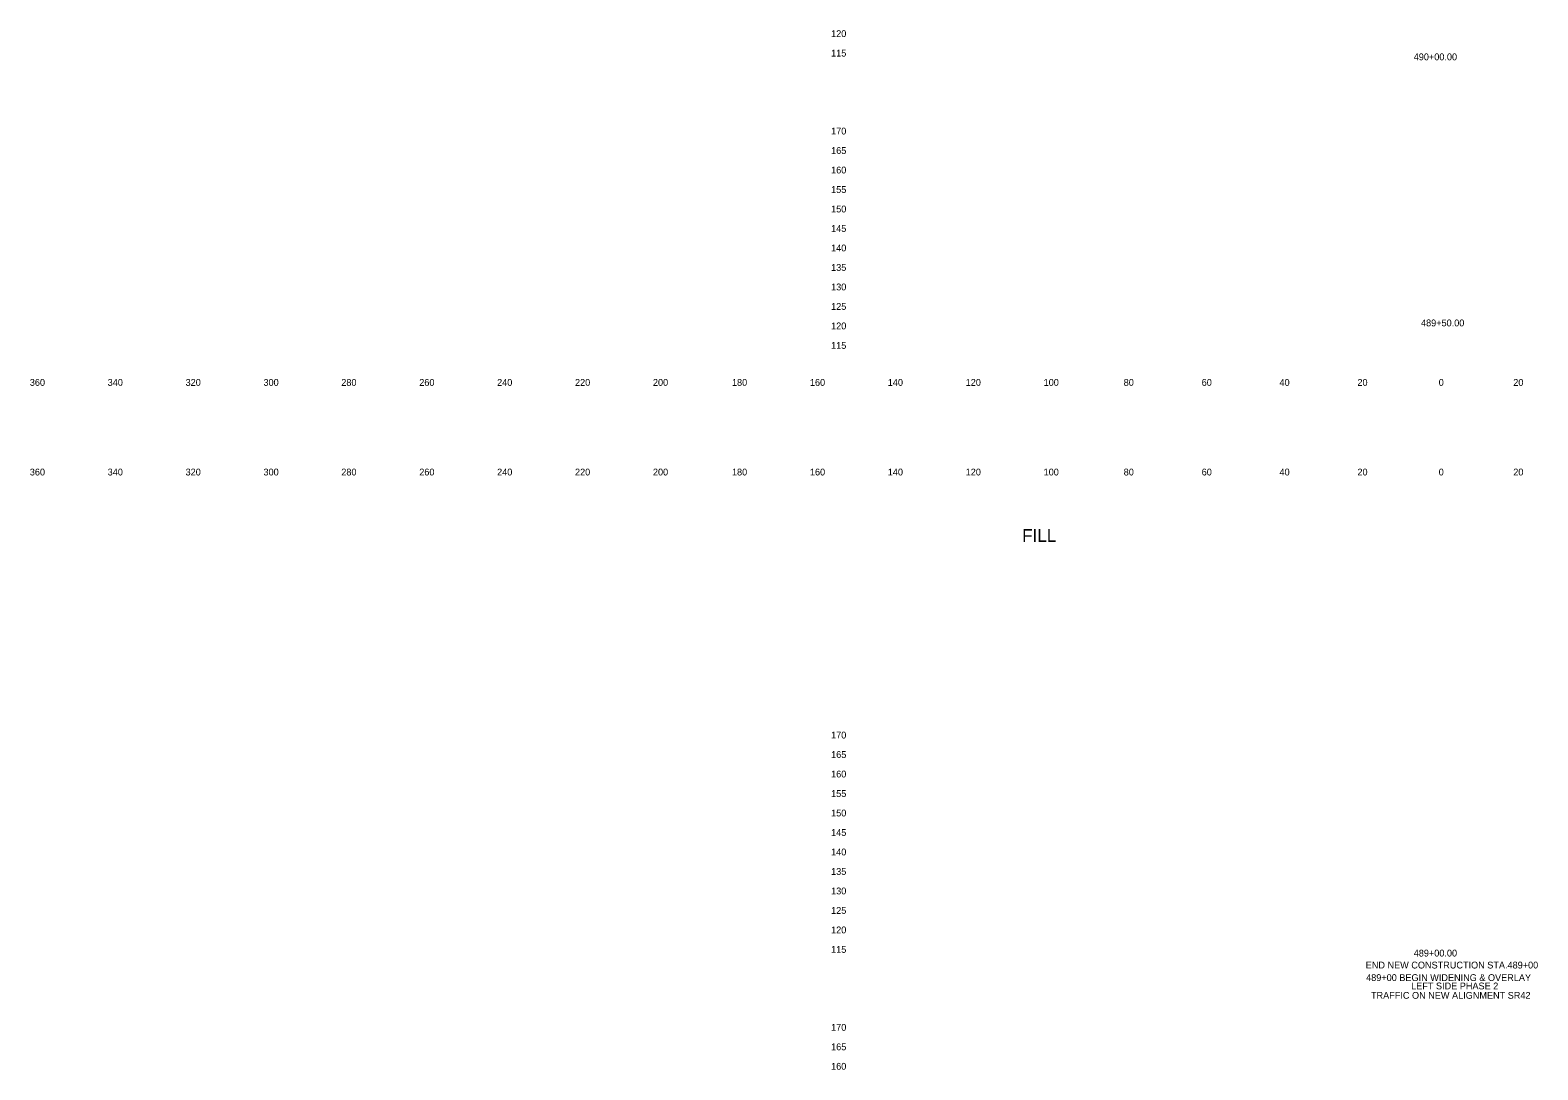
# Model space of a CAD drawing. Extents: x 21281 to 22024, y 6472 to 15208.
# Drawn here: x 21280.5 to 21667.6, y 14119.8 to 14386.6 of the extents above; entities that cross this region are included whole.
import ezdxf

# ---------------------------------------------------------------- set-up
doc = ezdxf.new("R2010")
doc.units = 0
for name, color, linetype in [('XS_SHEET_LABELS_ELEVATION', 7, 'Continuous'), ('XS_SHEET_LABELS_OFFSET', 7, 'Continuous'), ('XS_SHEET_LABELS_STATION', 7, 'Continuous')]:
    doc.layers.add(name, color=color, linetype=linetype)

msp = doc.modelspace()

# ---------------------------------------------------------------- texts
at = {"layer": 'XS_SHEET_LABELS_ELEVATION'}
for s, p in [('  120  ', (21484.84, 14384.84)), ('  115  ', (21484.84, 14379.84)), ('  170  ', (21484.84, 14359.84)), ('  165  ', (21484.84, 14354.84)), ('  160  ', (21484.84, 14349.84)), ('  155  ', (21484.84, 14344.84)), ('  150  ', (21484.84, 14339.84)), ('  145  ', (21484.84, 14334.84)), ('  140  ', (21484.84, 14329.84)), ('  135  ', (21484.84, 14324.84)), ('  130  ', (21484.84, 14319.84)), ('  125  ', (21484.84, 14314.84)), ('  120  ', (21484.84, 14309.84)), ('  115  ', (21484.84, 14304.84)), ('  170  ', (21484.84, 14204.84)), ('  165  ', (21484.84, 14199.84)), ('  160  ', (21484.84, 14194.84)), ('  155  ', (21484.84, 14189.84)), ('  150  ', (21484.84, 14184.84)), ('  145  ', (21484.84, 14179.84)), ('  140  ', (21484.84, 14174.84)), ('  135  ', (21484.84, 14169.84)), ('  130  ', (21484.84, 14164.84)), ('  125  ', (21484.84, 14159.84)), ('  120  ', (21484.84, 14154.84)), ('  115  ', (21484.84, 14149.84)), ('  170  ', (21484.84, 14129.84)), ('  165  ', (21484.84, 14124.84)), ('  160  ', (21484.84, 14119.84))]:
    msp.add_text(s, height=1.75, dxfattribs=at).set_placement(p)
at = {"layer": 'XS_SHEET_LABELS_OFFSET'}
for s, height, p in [('  360  ', 1.75, (21279.14, 14295.34)), ('  340  ', 1.75, (21299.13, 14295.34)), ('  320  ', 1.75, (21319.13, 14295.34)), ('  300  ', 1.75, (21339.13, 14295.34)), ('  280  ', 1.75, (21359.1, 14295.34)), ('  260  ', 1.75, (21379.11, 14295.34)), ('  240  ', 1.75, (21399.1, 14295.34)), ('  220  ', 1.75, (21419.1, 14295.34)), ('  200  ', 1.75, (21439.1, 14295.34)), ('  180  ', 1.75, (21459.39, 14295.34)), ('  160  ', 1.75, (21479.4, 14295.34)), ('  140  ', 1.75, (21499.39, 14295.34)), ('  120  ', 1.75, (21519.39, 14295.34)), ('  100  ', 1.75, (21539.39, 14295.34)), ('  80  ', 1.75, (21559.95, 14295.34)), ('  60  ', 1.75, (21579.97, 14295.34)), ('  40  ', 1.75, (21599.95, 14295.34)), ('  20  ', 1.75, (21619.95, 14295.34)), ('  0  ', 1.75, (21640.81, 14295.34)), ('  0  ', 1.75, (21640.81, 14295.34)), ('  20  ', 1.75, (21659.95, 14295.34)), ('  360  ', 1.75, (21279.14, 14272.34)), ('  340  ', 1.75, (21299.13, 14272.34)), ('  320  ', 1.75, (21319.13, 14272.34)), ('  300  ', 1.75, (21339.13, 14272.34)), ('  280  ', 1.75, (21359.1, 14272.34)), ('  260  ', 1.75, (21379.11, 14272.34)), ('  240  ', 1.75, (21399.1, 14272.34)), ('  220  ', 1.75, (21419.1, 14272.34)), ('  200  ', 1.75, (21439.1, 14272.34)), ('  180  ', 1.75, (21459.39, 14272.34)), ('  160  ', 1.75, (21479.4, 14272.34)), ('  140  ', 1.75, (21499.39, 14272.34)), ('  120  ', 1.75, (21519.39, 14272.34)), ('  100  ', 1.75, (21539.39, 14272.34)), ('  80  ', 1.75, (21559.95, 14272.34)), ('  60  ', 1.75, (21579.97, 14272.34)), ('  40  ', 1.75, (21599.95, 14272.34)), ('  20  ', 1.75, (21619.95, 14272.34)), ('  0  ', 1.75, (21640.81, 14272.34)), ('  0  ', 1.75, (21640.81, 14272.34)), ('  20  ', 1.75, (21659.95, 14272.34)), ('FILL', 3.273, (21535.18, 14255.29))]:
    msp.add_text(s, height=height, dxfattribs=at).set_placement(p)
at = {"layer": 'XS_SHEET_LABELS_STATION'}
for s, p in [('  490+00.00  ', (21634.4, 14378.89)), ('  489+50.00  ', (21636.27, 14310.61)), ('  489+00.00  ', (21634.4, 14148.89)), ('  489+00.00  ', (21634.4, 14148.89)), ('  489+00.00  ', (21634.4, 14148.89)), ('END NEW CONSTRUCTION STA.489+00 ', (21623.38, 14145.82)), (' 489+00 BEGIN WIDENING & OVERLAY', (21622.83, 14142.6)), ('TRAFFIC ON NEW ALIGNMENT SR42', (21624.73, 14138.05)), ('LEFT SIDE PHASE 2', (21635.04, 14140.46))]:
    msp.add_text(s, height=1.75, dxfattribs=at).set_placement(p)

doc.saveas('drawing.dxf')
